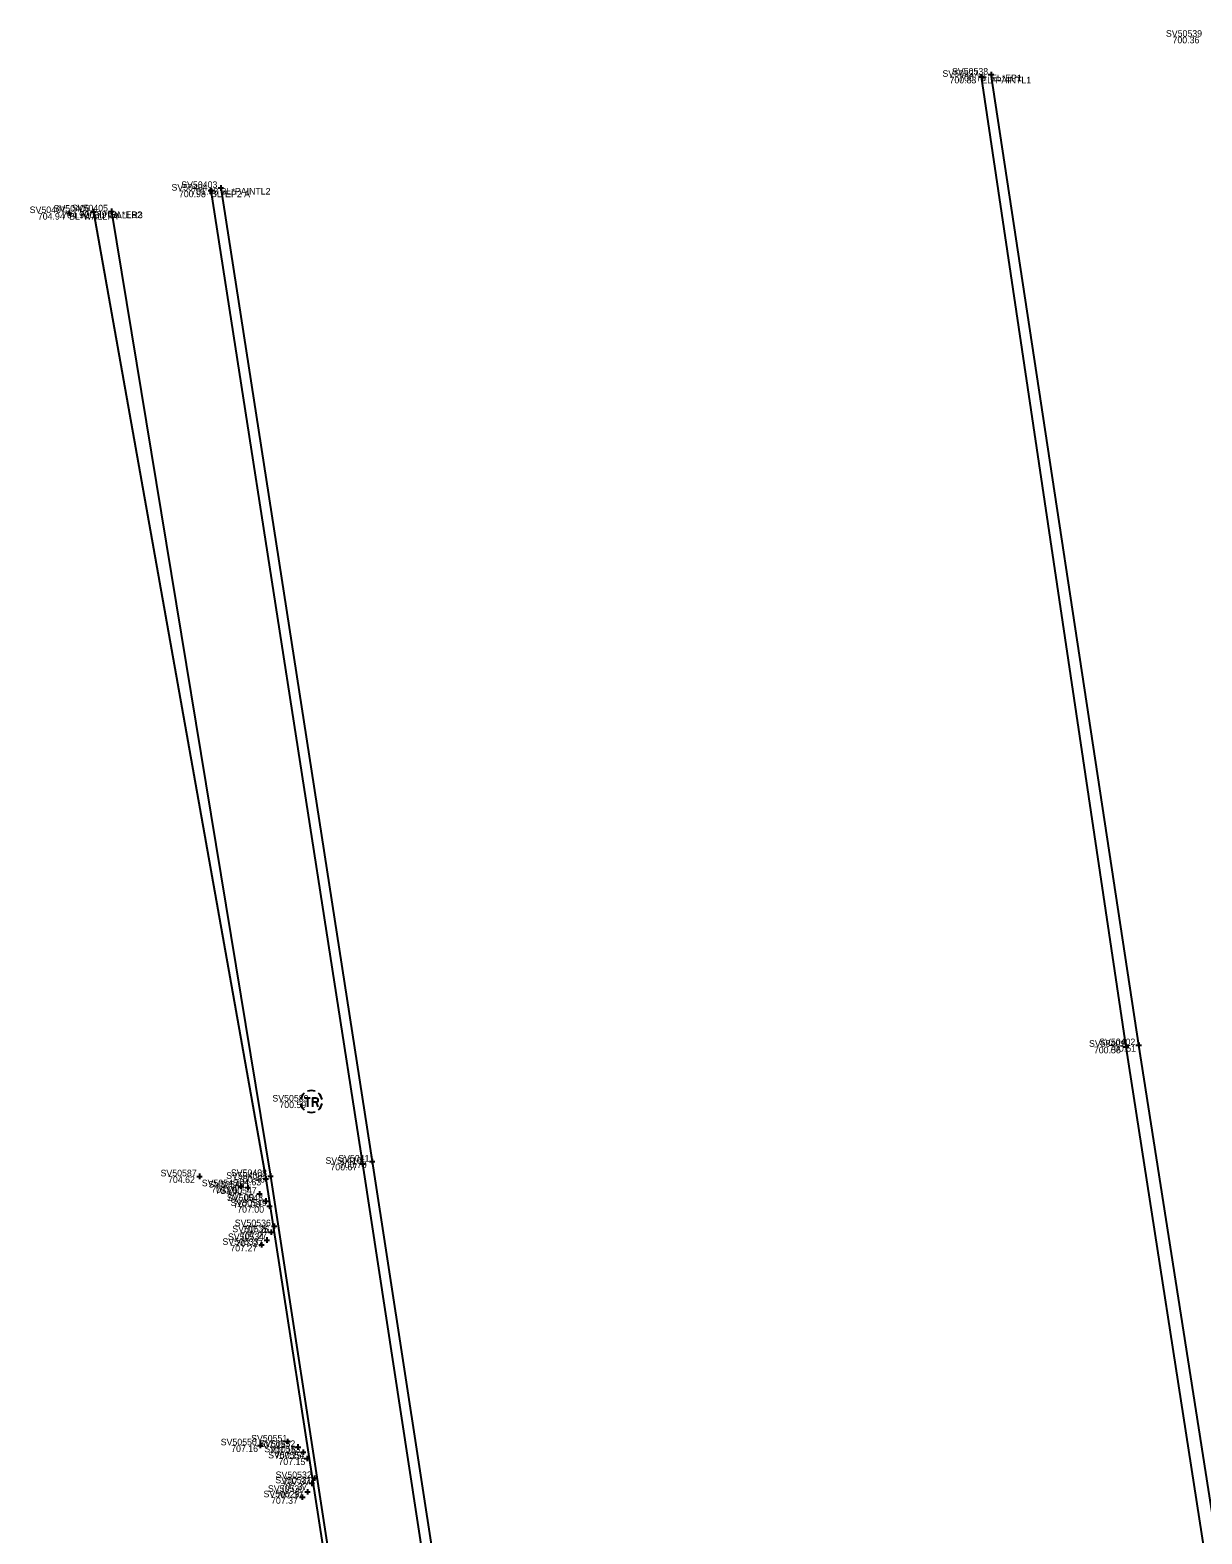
# Model space of a CAD drawing. Extents: x 182090 to 1832865, y 706265 to 714392.
# Drawn here: x 1823058.7 to 1823112.3, y 714322.8 to 714391.5 of the extents above; entities that cross this region are included whole.
import ezdxf

# ---------------------------------------------------------------- set-up
doc = ezdxf.new("R2010")
doc.units = 0
for name, color, linetype in [('BR_X_SV_Pier_Text', 7, 'Continuous'), ('PV_X_EOP', 7, 'Continuous'), ('PV_X_Shoulder', 7, 'Continuous'), ('RD_X_Wall', 7, 'Continuous'), ('SG_X_Manhole', 7, 'Continuous'), ('SV_X_Shot_Marker', 7, 'Continuous'), ('SV_X_Text_Comment', 7, 'Continuous'), ('SV_X_Text_Elevation', 7, 'Continuous'), ('SV_X_Text_Name', 7, 'Continuous')]:
    doc.layers.add(name, color=color, linetype=linetype)

msp = doc.modelspace()

# ---------------------------------------------------------------- linework, layer by layer
at = {"layer": 'BR_X_SV_Pier_Text'}
for p, q in [((1823068.322, 714338.805), (1823068.322, 714338.555)), ((1823068.644, 714338.747), (1823068.644, 714338.497)), ((1823068.197, 714338.68), (1823068.447, 714338.68)), ((1823068.322, 714338.68), (1823068.322, 714338.68)), ((1823068.519, 714338.622), (1823068.769, 714338.622)), ((1823068.644, 714338.622), (1823068.644, 714338.622)), ((1823069.055, 714338.338), (1823069.305, 714338.338)), ((1823069.18, 714338.463), (1823069.18, 714338.213)), ((1823069.18, 714338.338), (1823069.18, 714338.338)), ((1823069.472, 714338.13), (1823069.472, 714337.88)), ((1823069.347, 714338.005), (1823069.597, 714338.005)), ((1823069.472, 714338.005), (1823069.472, 714338.005)), ((1823069.517, 714337.774), (1823069.767, 714337.774)), ((1823069.642, 714337.899), (1823069.642, 714337.649)), ((1823069.642, 714337.774), (1823069.642, 714337.774)), ((1823069.72, 714336.705), (1823069.72, 714336.455)), ((1823069.725, 714336.857), (1823069.975, 714336.857)), ((1823069.85, 714336.982), (1823069.85, 714336.732)), ((1823069.85, 714336.857), (1823069.85, 714336.857)), ((1823069.144, 714336.001), (1823069.394, 714336.001)), ((1823069.269, 714336.126), (1823069.269, 714335.876)), ((1823069.269, 714336.001), (1823069.269, 714336.001)), ((1823069.393, 714336.222), (1823069.643, 714336.222)), ((1823069.518, 714336.347), (1823069.518, 714336.097)), ((1823069.518, 714336.222), (1823069.518, 714336.222)), ((1823069.595, 714336.58), (1823069.845, 714336.58)), ((1823069.72, 714336.58), (1823069.72, 714336.58)), ((1823070.466, 714327.138), (1823070.466, 714326.888)), ((1823069.087, 714326.84), (1823069.337, 714326.84)), ((1823069.212, 714326.965), (1823069.212, 714326.715)), ((1823069.212, 714326.84), (1823069.212, 714326.84)), ((1823070.341, 714327.013), (1823070.591, 714327.013)), ((1823070.466, 714327.013), (1823070.466, 714327.013)), ((1823070.815, 714326.763), (1823071.065, 714326.763)), ((1823070.94, 714326.888), (1823070.94, 714326.638)), ((1823070.94, 714326.763), (1823070.94, 714326.763)), ((1823071.051, 714326.526), (1823071.301, 714326.526)), ((1823071.176, 714326.651), (1823071.176, 714326.401)), ((1823071.176, 714326.526), (1823071.176, 714326.526)), ((1823071.353, 714326.368), (1823071.353, 714326.118)), ((1823071.228, 714326.243), (1823071.478, 714326.243)), ((1823071.353, 714326.243), (1823071.353, 714326.243)), ((1823071.451, 714325.104), (1823071.701, 714325.104)), ((1823071.572, 714325.344), (1823071.822, 714325.344)), ((1823071.576, 714325.229), (1823071.576, 714324.979)), ((1823071.576, 714325.104), (1823071.576, 714325.104)), ((1823071.697, 714325.469), (1823071.697, 714325.219)), ((1823071.697, 714325.344), (1823071.697, 714325.344)), ((1823071.013, 714324.468), (1823071.263, 714324.468)), ((1823071.138, 714324.593), (1823071.138, 714324.343)), ((1823071.138, 714324.468), (1823071.138, 714324.468)), ((1823071.249, 714324.712), (1823071.499, 714324.712)), ((1823071.374, 714324.837), (1823071.374, 714324.587)), ((1823071.374, 714324.712), (1823071.374, 714324.712))]:
    msp.add_line(p, q, dxfattribs=at)
at = {"layer": 'PV_X_EOP'}
for points in [[(1823213.293, 713745.175), (1823205.405, 713788.669), (1823198.567, 713826.449), (1823190.488, 713870.707), (1823182.354, 713915.03), (1823174.241, 713959.25), (1823165.984, 714003.65), (1823156.504, 714055.601), (1823154.113, 714068.55), (1823146.265, 714112.428), (1823138.217, 714157.991), (1823131.409, 714200.09), (1823124.618, 714244.15), (1823117.566, 714288.492), (1823108.791, 714345.054), (1823102.174, 714389.381)], [(1823067.411, 714384.301), (1823074.33, 714339.808), (1823082.996, 714283.475), (1823089.982, 714239.194), (1823096.89, 714194.536), (1823103.258, 714152.585), (1823110.091, 714107.757), (1823116.766, 714064.256), (1823123.627, 714020.322), (1823127.152, 713997.797), (1823134.144, 713953.07), (1823140.806, 713909.017), (1823147.808, 713863.803), (1823154.619, 713819.776), (1823160.498, 713780.578), (1823166.856, 713739.218)]]:
    msp.add_lwpolyline(points, dxfattribs=at)
at = {"layer": 'PV_X_Shoulder'}
for points in [[(1823213.884, 713745.334), (1823205.943, 713788.697), (1823198.98, 713826.676), (1823190.908, 713870.798), (1823182.824, 713915.082), (1823174.692, 713959.552), (1823166.602, 714003.788), (1823157.028, 714055.711), (1823154.691, 714068.651), (1823146.758, 714112.546), (1823138.452, 714158.082), (1823131.801, 714200.169), (1823125.085, 714244.224), (1823118.23, 714288.583), (1823109.362, 714345.129), (1823102.614, 714389.48)], [(1823066.963, 714384.179), (1823073.884, 714339.706), (1823082.531, 714283.432), (1823089.436, 714239.039), (1823096.303, 714194.298), (1823102.729, 714152.565), (1823109.685, 714107.704), (1823116.355, 714064.136), (1823123.167, 714020.282), (1823126.577, 713997.667), (1823133.71, 713952.915), (1823140.397, 713908.841), (1823147.297, 713863.766), (1823154.059, 713819.612), (1823160.042, 713780.464), (1823166.25, 713739.132)], [(1823062.412, 714383.232), (1823069.681, 714339.147), (1823078.395, 714282.679), (1823084.433, 714243.032), (1823084.92, 714239.593), (1823085.365, 714236.389), (1823086.098, 714231.409), (1823090.212, 714205.117), (1823091.46, 714196.938), (1823091.983, 714193.775), (1823093.358, 714185.385), (1823098.276, 714152.285), (1823105.324, 714106.822), (1823112.064, 714062.977), (1823118.667, 714019.979), (1823122.178, 713997.02), (1823129.16, 713952.197), (1823135.792, 713909.032), (1823142.968, 713863.089), (1823149.523, 713818.954), (1823155.672, 713779.387), (1823161.978, 713738.44)]]:
    msp.add_lwpolyline(points, dxfattribs=at)
at = {"layer": 'RD_X_Wall'}
msp.add_lwpolyline([(1823061.595, 714383.217), (1823069.468, 714339.018), (1823078.164, 714283.052), (1823082.401, 714255.587), (1823084.562, 714239.744), (1823089.217, 714204.87), (1823096.881, 714152.352), (1823104.192, 714106.778), (1823110.948, 714062.926), (1823117.647, 714019.685), (1823121.082, 713997.094), (1823128.068, 713952.108), (1823134.675, 713909.088), (1823141.916, 713862.871), (1823148.554, 713818.502), (1823154.647, 713778.964), (1823160.909, 713738.092)], dxfattribs=at)
at = {"layer": 'SG_X_Manhole'}
msp.add_line((1823071.55, 714342.552), (1823071.55, 714342.552), dxfattribs=at)
for points in [[(1823071.245, 714342.715), (1823071.493, 714342.715)], [(1823071.371, 714342.715), (1823071.371, 714342.315)], [(1823071.619, 714342.315), (1823071.619, 714342.715), (1823071.77, 714342.715), (1823071.786, 714342.711), (1823071.808, 714342.705), (1823071.818, 714342.699), (1823071.827, 714342.693), (1823071.84, 714342.677), (1823071.849, 714342.661), (1823071.855, 714342.636), (1823071.855, 714342.598), (1823071.852, 714342.585), (1823071.846, 714342.567), (1823071.833, 714342.545), (1823071.821, 714342.535), (1823071.811, 714342.529), (1823071.805, 714342.526), (1823071.796, 714342.522), (1823071.767, 714342.519), (1823071.619, 714342.519)], [(1823071.767, 714342.519), (1823071.855, 714342.315)]]:
    msp.add_lwpolyline(points, dxfattribs=at)
for start, end in [(130.0806, 170.07213), (70.05767, 110.10608), (10.01689, 50.03919), (190.01689, 230.03919), (310.01144, 350.02638), (250.05767, 290.04731)]:
    msp.add_arc((1823071.55, 714342.552), 0.5, start, end, dxfattribs=at)
at = {"layer": 'SV_X_Shot_Marker'}
for p, q in [((1823102.614, 714389.605), (1823102.614, 714389.355)), ((1823102.049, 714389.381), (1823102.299, 714389.381)), ((1823102.174, 714389.506), (1823102.174, 714389.256)), ((1823102.174, 714389.381), (1823102.174, 714389.381)), ((1823102.489, 714389.48), (1823102.739, 714389.48)), ((1823102.614, 714389.48), (1823102.614, 714389.48)), ((1823066.838, 714384.179), (1823067.088, 714384.179)), ((1823066.963, 714384.304), (1823066.963, 714384.054)), ((1823066.963, 714384.179), (1823066.963, 714384.179)), ((1823067.286, 714384.301), (1823067.536, 714384.301)), ((1823067.411, 714384.426), (1823067.411, 714384.176)), ((1823067.411, 714384.301), (1823067.411, 714384.301)), ((1823060.36, 714383.153), (1823060.61, 714383.153)), ((1823060.485, 714383.278), (1823060.485, 714383.028)), ((1823060.485, 714383.153), (1823060.485, 714383.153)), ((1823061.47, 714383.217), (1823061.72, 714383.217)), ((1823061.595, 714383.342), (1823061.595, 714383.092)), ((1823061.595, 714383.217), (1823061.595, 714383.217)), ((1823062.287, 714383.232), (1823062.537, 714383.232)), ((1823062.412, 714383.357), (1823062.412, 714383.107)), ((1823062.412, 714383.232), (1823062.412, 714383.232)), ((1823108.666, 714345.054), (1823108.916, 714345.054)), ((1823108.791, 714345.179), (1823108.791, 714344.929)), ((1823108.791, 714345.054), (1823108.791, 714345.054)), ((1823109.237, 714345.129), (1823109.487, 714345.129)), ((1823109.362, 714345.254), (1823109.362, 714345.004)), ((1823109.362, 714345.129), (1823109.362, 714345.129)), ((1823073.759, 714339.706), (1823074.009, 714339.706)), ((1823073.884, 714339.831), (1823073.884, 714339.581)), ((1823073.884, 714339.706), (1823073.884, 714339.706)), ((1823074.205, 714339.808), (1823074.455, 714339.808)), ((1823074.33, 714339.933), (1823074.33, 714339.683)), ((1823074.33, 714339.808), (1823074.33, 714339.808)), ((1823066.31, 714339.133), (1823066.56, 714339.133)), ((1823066.435, 714339.258), (1823066.435, 714339.008)), ((1823066.435, 714339.133), (1823066.435, 714339.133)), ((1823069.343, 714339.018), (1823069.593, 714339.018)), ((1823069.468, 714339.143), (1823069.468, 714338.893)), ((1823069.468, 714339.018), (1823069.468, 714339.018)), ((1823069.556, 714339.147), (1823069.806, 714339.147)), ((1823069.681, 714339.272), (1823069.681, 714339.022)), ((1823069.681, 714339.147), (1823069.681, 714339.147))]:
    msp.add_line(p, q, dxfattribs=at)

# ---------------------------------------------------------------- texts
at = {"layer": 'BR_X_SV_Pier_Text'}
for s, p in [('SV50545', (1823066.543, 714338.68)), ('SV50546', (1823066.847, 714338.622)), ('707.01', (1823066.978, 714338.38)), ('707.00', (1823067.165, 714338.322)), ('SV50547', (1823067.401, 714338.338)), ('SV50548', (1823067.691, 714338.005)), ('707.00', (1823067.701, 714338.038)), ('SV50549', (1823067.861, 714337.774)), ('707.00', (1823067.993, 714337.705)), ('707.00', (1823068.163, 714337.474)), ('SV50535', (1823067.939, 714336.58)), ('SV50536', (1823068.05, 714336.857)), ('707.26', (1823068.412, 714336.557)), ('SV50533', (1823067.488, 714336.001)), ('SV50534', (1823067.739, 714336.222)), ('707.27', (1823067.849, 714335.701)), ('707.27', (1823068.098, 714335.922)), ('707.27', (1823068.3, 714336.28)), ('SV50550', (1823067.41, 714326.84)), ('SV50551', (1823068.799, 714327.013)), ('SV50552', (1823069.166, 714326.763)), ('707.16', (1823067.887, 714326.54)), ('707.15', (1823069.16, 714326.713)), ('SV50553', (1823069.4, 714326.526)), ('SV50554', (1823069.579, 714326.243)), ('707.15', (1823069.634, 714326.463)), ('707.15', (1823069.87, 714326.226)), ('707.15', (1823070.047, 714325.943)), ('SV50530', (1823069.567, 714324.712)), ('SV50531', (1823069.904, 714325.104)), ('SV50532', (1823069.918, 714325.344)), ('707.37', (1823070.147, 714324.804)), ('707.37', (1823070.268, 714325.044)), ('SV50529', (1823069.364, 714324.468)), ('707.37', (1823069.709, 714324.168)), ('707.37', (1823069.945, 714324.412))]:
    msp.add_text(s, height=0.3, dxfattribs=at).set_placement(p)
at = {"layer": 'SV_X_Text_Comment'}
for s, p in [('EL*PAINTL1', (1823102.174, 714389.081)), ('EL*EP1', (1823102.614, 714389.18)), ('BL*EP2 A', (1823066.963, 714383.879)), ('BL*PAINTL2', (1823067.411, 714384.001)), ('BL*WALLR4', (1823060.485, 714382.853)), ('BL*WALLR3', (1823061.595, 714382.917)), ('BL*EB2', (1823062.412, 714382.932))]:
    msp.add_text(s, height=0.3, dxfattribs=at).set_placement(p)
at = {"layer": 'SV_X_Text_Elevation'}
for s, p in [('700.36', (1823110.91, 714390.912)), ('700.83', (1823100.717, 714389.081)), ('700.79', (1823101.159, 714389.18)), ('700.98', (1823065.499, 714383.879)), ('701.08', (1823066.069, 714384.001)), ('704.94', (1823059.051, 714382.853)), ('704.92', (1823060.161, 714382.917)), ('700.79', (1823060.957, 714382.932)), ('700.56', (1823107.315, 714344.754)), ('700.51', (1823108.014, 714344.829)), ('700.59', (1823070.09, 714342.252)), ('700.67', (1823072.422, 714339.406)), ('700.70', (1823072.851, 714339.508)), ('704.62', (1823065.001, 714338.833)), ('704.63', (1823068.032, 714338.718)), ('700.46', (1823068.202, 714338.847))]:
    msp.add_text(s, height=0.3, dxfattribs=at).set_placement(p)
at = {"layer": 'SV_X_Text_Name'}
for s, p in [('SV50539', (1823110.608, 714391.212)), ('SV50537', (1823100.393, 714389.381)), ('SV50538', (1823100.831, 714389.48)), ('SV50404', (1823065.158, 714384.179)), ('SV50403', (1823065.604, 714384.301)), ('SV50407', (1823058.678, 714383.153)), ('SV50406', (1823059.769, 714383.217)), ('SV50405', (1823060.605, 714383.232)), ('SV50401', (1823107.093, 714345.054)), ('SV50402', (1823107.557, 714345.129)), ('SV50589', (1823069.771, 714342.552)), ('SV50411', (1823072.779, 714339.808)), ('SV50587', (1823064.659, 714339.133)), ('SV50408', (1823067.872, 714339.147)), ('SV50410', (1823072.198, 714339.706)), ('SV50409', (1823067.659, 714339.018))]:
    msp.add_text(s, height=0.3, dxfattribs=at).set_placement(p)

doc.saveas('drawing.dxf')
